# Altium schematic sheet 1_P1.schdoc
size 431 x 309 mm; Symbol: Sheet-Symbol_A3; Device: Sheet-Symbol_A3; Convert to PCB: yes; Add into BOM: yes; @Project Name: CV工程师专用键盘; @Page Count: 1; @Update Date: 2022-08-17; @Create Date: 2022-08-17; @Schematic Name: Schematic2; @Page No: 1; @Page Name: P1
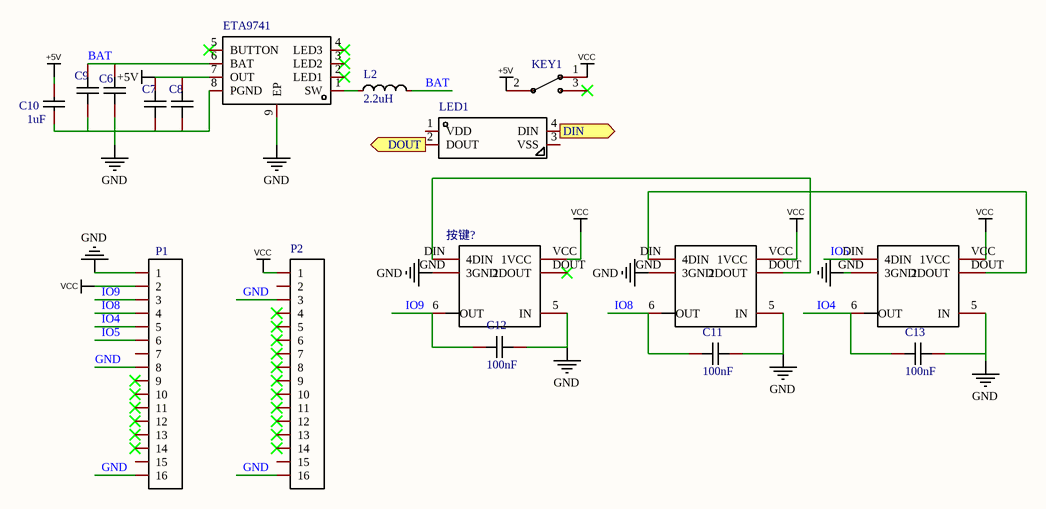
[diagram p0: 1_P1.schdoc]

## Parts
C6  0603  [C0603]  (value not drawn)
C7  0805  [C0805]  (value not drawn)
C8  0805  [C0805]  (value not drawn)
C9  0603  [C0603]  (value not drawn)
C10  value 1uF  [C0603_3]  (hidden comment: 0603 1uf)
C11  value 100nF  [C0603]  (hidden comment: 0603 100nf)
C12  value 100nF  [C0603]  (hidden comment: 0603 100nf)
C13  value 100nF  [C0603]  (hidden comment: 0603 100nf)
ETA9741  ETA9741  [SOIC-8_L4.9-W3.9-P1.27-LS6.0-BL-EP2.9]  (value not drawn)
KEY1  MSK-12C02  [MSK-11027]  (value not drawn)
L2  value 2.2uH  [IND-SMD_L4.4-W4.2]  (hidden comment: 0420CDMCCDS-2R2MC)
LED1  WS2812B-B  [LED-SMD_4P-L5.0-W5.0-TL_WS2812B-B]  (value not drawn)
P1  2.54-1*16P母  [HDR-TH_16P-P2.54-V-F-1]  (value not drawn)
P2  2.54-1*16P母  [HDR-TH_16P-P2.54-V-F-1]  (value not drawn)
U1  KAILH_WS2182B_3528反贴_无二极管  [KAILH_WS2182B_3528反贴_无二极管_封装]  (value not drawn)
U2  KAILH_WS2182B_3528反贴_无二极管  [KAILH_WS2182B_3528反贴_无二极管_封装]  (value not drawn)
按键?  KAILH_WS2182B_3528反贴_无二极管  [KAILH_WS2182B_3528反贴_无二极管_封装]  (value not drawn)

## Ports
DIN (out), DOUT (out)

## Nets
+5V: C7.1 C8.1 C10.2 ETA9741.7(OUT) KEY1.2
GND: C6.1 C7.2 C8.2 C9.1 C10.1 C11.2 C12.2 C13.2 ETA9741.8(PGND) ETA9741.9(EP) P1.1 P1.8 P1.16 P2.3 P2.16 U1.5(IN) U1.GND(3GND) U2.5(IN) 按键?.5(IN) 按键?.GND(3GND)
VCC: KEY1.1 P1.2 P2.1 U1.VCC(1VCC) U2.VCC(1VCC) 按键?.VCC(1VCC)
BAT: C6.2 C9.2 ETA9741.6(BAT) L2.2
DIN: LED1.4(DIN) ; port DIN
DOUT: LED1.2(DOUT) ; port DOUT
IO4: C13.1 P1.5 U2.6(OUT)
IO5: P1.6 U2.DIN(4DIN)
IO8: C11.1 P1.4 U1.6(OUT)
IO9: C12.1 P1.3 按键?.6(OUT)
NetETA9741_1: ETA9741.1(SW) L2.1
NetU1_DIN: U1.DIN(4DIN) U2.DOUT(2DOUT)
NetU1_DOUT: U1.DOUT(2DOUT) 按键?.DIN(4DIN)

Not connected (* = marked no-connect by the designer): ETA9741 2(LED1)* 3(LED2)* 4(LED3)* 5(BUTTON)*; KEY1 3*; LED1 1(VDD) 3(VSS); P1 7 9* 10* 11* 12* 13* 14* 15; P2 2 4* 5* 6* 7* 8* 9* 10* 11* 12* 13* 14* 15; U2 GND(3GND); 按键? DOUT(2DOUT)*

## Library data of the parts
C6 C9 = 0603: Symbol: 0603_C9900021180; Add into BOM: yes
C7 C8 = 0805: Symbol: 0805_C9900012713; Add into BOM: yes
C10 = 0603 1uf: 温度系数:X5R;精度:±10%;额定电压:50V;容值:1uF;; Manufacturer: SAMSUNG(三星); Manufacturer Part: CL10A105KB8NNNC; Symbol: CL10A105KB8NNNC_1; Add into BOM: yes; Temperature Coefficient: X5R; Tolerance: ±10%; Voltage Rated: 50V
C11-C13 = 0603 100nf: 容值:100nF;精度:±10%;额定电压:50V;材质(温度系数):X7R;; Manufacturer: YAGEO(国巨); Symbol: CC0603KRX7R9BB104; Add into BOM: yes; Tolerance: ±10%; Voltage Rated: 50V; Temperature Coefficient: X7R
ETA9741 = ETA9741: Pin Type: IN; Add into BOM: yes
KEY1 = MSK-12C02: Manufacturer: SHOU HAN; Name: MSK12C02; Add into BOM: yes
L2 = 0420CDMCCDS-2R2MC: 电感值:2.2uH;精度:±20%;额定电流:4.3A;饱和电流(Isat):5.4A;直流电阻(DCR):52mΩ;; Manufacturer: Sumida(胜美达); Add into BOM: yes; Tolerance: ±20%; Rated Current: 4.3A; Saturation Current (Isat): 5.4A; DC Resistance (DCR): 52mΩ
LED1 = WS2812B-B: 发光颜色:RGB三色;; Manufacturer: worldsemi; Add into BOM: yes; Emitted Color: RGB三色
P1 P2 = 2.54-1*16P母: 间距:2.54mm;总孔位数:16;排数:1;行距:-;安装类型:直插;塑高:-;触头材质:-;触头镀层:-;; Manufacturer: BOOMELE(博穆精密); Symbol: Header-Female-2.54_1x16; Add into BOM: yes; Pitch: 2.54mm; Number of Holes: 16
U1 U2 按键? = KAILH_WS2182B_3528反贴_无二极管: Symbol: KAILH_WS2182B_3528反贴_无二极管-符号; Convert to PCB: yes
